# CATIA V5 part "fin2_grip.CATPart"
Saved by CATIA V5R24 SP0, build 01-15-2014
Part number: Grip
Bounding box of the stored display mesh (mm): x 0 to 2.5, y 0 to 13.75, z -7.5 to 0
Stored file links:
  G:\내 드라이브\04_WORK\00_LECTURE\CAD2020\exam\fin2_grip.CATPart
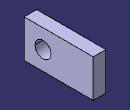
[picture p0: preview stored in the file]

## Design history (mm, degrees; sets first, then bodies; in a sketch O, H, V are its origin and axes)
Body1 (main body)
  Sketch1 on yz-plane, origin (0, 0, 0), H (0, 1, 0), V (0, 0, 1)
    line L1 (0, 0) -> (13.75, 0)
    line L2 (13.75, 0) -> (13.75, -7.5)
    line L3 (13.75, -7.5) -> (0, -7.5)
    line L4 (0, -7.5) -> (0, 0)
    construction line L5 (-3.9723, -3.75) -> (23.0681, -3.75)
    axis line L6 (3.75, 4.9145) -> (3.75, -12.4145)
    circle A1 centre (3.75, -3.75) radius 1.6
    point P8 (3.75, -3.75)
    length L2 = 7.5
    length L3 = 13.75
    distance L5 L1 = 3.75
    distance L6 V = 3.75
    radius A1 = 1.6
    horizontal: L1 H, L3 H, L5 H
    vertical: L2 V, L4 V, L6 V
    midpoint: P8 L6
    coincidence: P8 L5
  Pad1: profile Sketch1, direction (1, 0, 0), length 2.5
